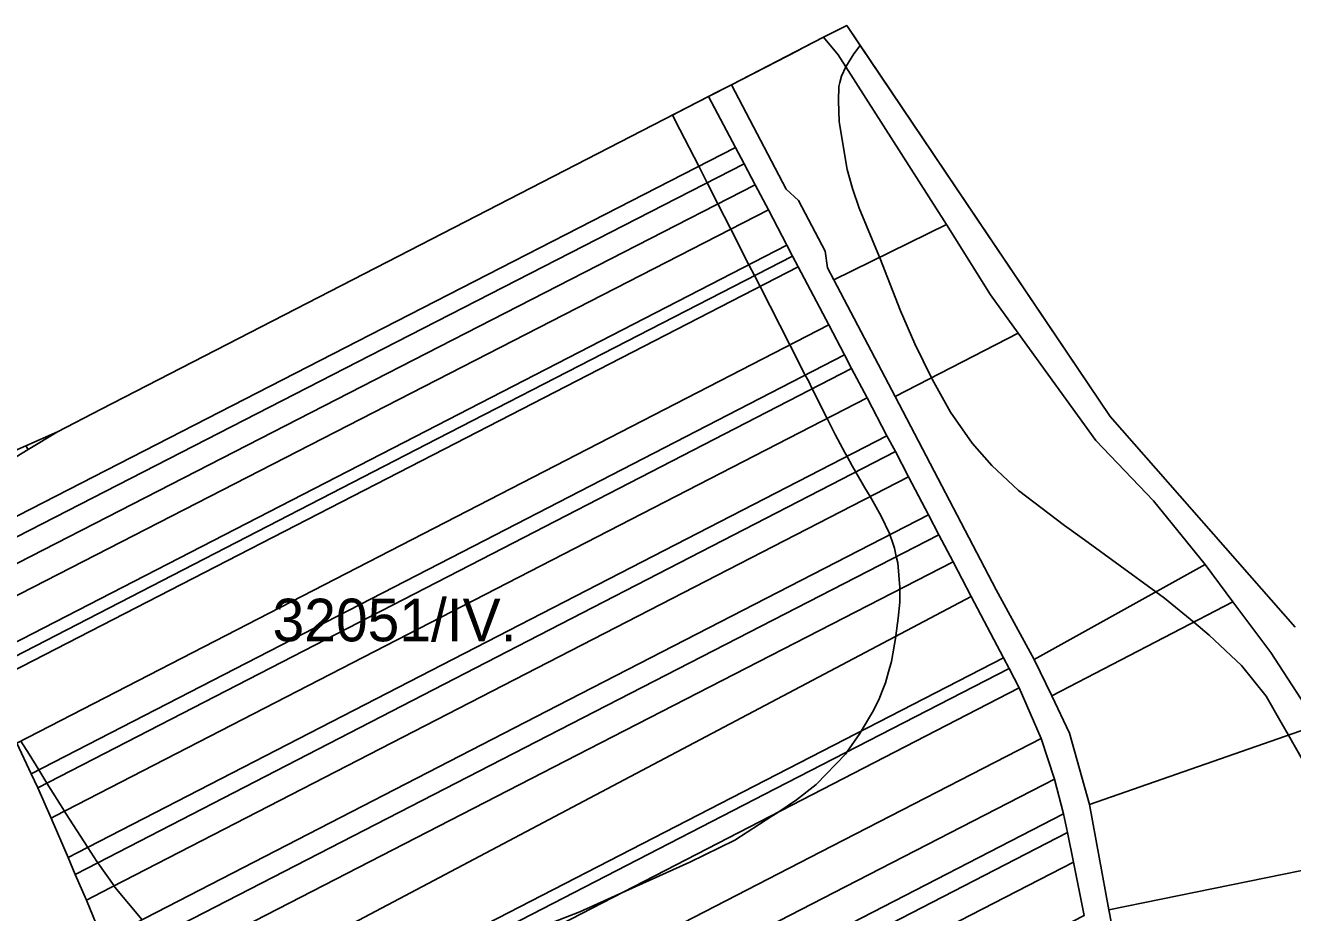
# Model space of a CAD drawing. Extents: x -521939 to -516426, y -1197857 to -1189551.
# Drawn here: x -520824.9 to -520378.7, y -1189863.1 to -1189550.7 of the extents above; entities that cross this region are included whole.
import ezdxf

# ---------------------------------------------------------------- set-up
doc = ezdxf.new("R2010")
doc.units = 0
for name, color, linetype in [('95560013', 7, 'Continuous'), ('95640013', 7, 'Continuous'), ('95660013', 7, 'Continuous')]:
    doc.layers.add(name, color=color, linetype=linetype)

msp = doc.modelspace()

# ---------------------------------------------------------------- linework, layer by layer
at = {"layer": '95560013'}
for points in [[(-520552.66, -1189612.4), (-520557.02, -1189608.4), (-520576.33, -1189571.62), (-520543.9, -1189554.92), (-520538.7, -1189561.06), (-520500.57, -1189620.82), (-520540.29, -1189640.25), (-520542.46, -1189636.12), (-520543.28, -1189630.26)], [(-520871.46, -1189729.85), (-520861.25, -1189722.78), (-520845.5, -1189713.21), (-520835.28, -1189707), (-520830.24, -1189703.94), (-520823.89, -1189700.08), (-520813.62, -1189693.84), (-520798.15, -1189685.87), (-520693.52, -1189631.98), (-520584.33, -1189575.74), (-520574.91, -1189593.69), (-520698.86, -1189657.27), (-520862.97, -1189741.45)], [(-520574.91, -1189593.69), (-520571.87, -1189599.49), (-520698.91, -1189664.62), (-520859.09, -1189746.74), (-520862.97, -1189741.45), (-520698.86, -1189657.27)], [(-520571.87, -1189599.49), (-520567.98, -1189606.88), (-520692.96, -1189670.96), (-520854.49, -1189753.78), (-520859.09, -1189746.74), (-520698.91, -1189664.62)], [(-520567.98, -1189606.88), (-520563.29, -1189615.69), (-520689.07, -1189680.22), (-520848.98, -1189762.26), (-520854.49, -1189753.78), (-520692.96, -1189670.96)], [(-520563.29, -1189615.69), (-520556.78, -1189628.12), (-520695.46, -1189699.52), (-520842.22, -1189775.08), (-520848.98, -1189762.26), (-520689.07, -1189680.22)], [(-520475.34, -1189659.1), (-520518.67, -1189681.41), (-520540.29, -1189640.25), (-520500.57, -1189620.82), (-520485.08, -1189645.55)], [(-520556.78, -1189628.12), (-520554.77, -1189631.94), (-520679.88, -1189696.34), (-520840.25, -1189778.89), (-520842.22, -1189775.08), (-520695.46, -1189699.52)], [(-520554.77, -1189631.94), (-520552.78, -1189635.77), (-520677.43, -1189699.92), (-520838.28, -1189782.7), (-520840.25, -1189778.89), (-520679.88, -1189696.34)], [(-520552.78, -1189635.77), (-520542.06, -1189656.2), (-520665.51, -1189719.78), (-520827.89, -1189803.41), (-520838.28, -1189782.7), (-520677.43, -1189699.92)], [(-520542.06, -1189656.2), (-520536.5, -1189666.75), (-520663.27, -1189732.03), (-520822.82, -1189814.19), (-520827.89, -1189803.41), (-520665.51, -1189719.78)], [(-520483.13, -1189749.49), (-520518.67, -1189681.41), (-520475.34, -1189659.1), (-520448.02, -1189696.82), (-520427.67, -1189718.16), (-520409.45, -1189740.47), (-520469.68, -1189773.95)], [(-520536.5, -1189666.75), (-520533.97, -1189671.56), (-520660.56, -1189736.75), (-520820.55, -1189819.14), (-520822.82, -1189814.19), (-520663.27, -1189732.03)], [(-520533.97, -1189671.56), (-520528.55, -1189681.89), (-520655.3, -1189747.14), (-520814.5, -1189829.1), (-520815.85, -1189829.79), (-520820.55, -1189819.14), (-520660.56, -1189736.75)], [(-520528.55, -1189681.89), (-520521.58, -1189695.28), (-520650.79, -1189761.81), (-520806.61, -1189842.04), (-520809.87, -1189843.72), (-520815.85, -1189829.79), (-520814.5, -1189829.1), (-520655.3, -1189747.14)], [(-520824.7, -1189698.73), (-520813.62, -1189693.84), (-520823.89, -1189700.08)], [(-520830.24, -1189703.94), (-520831.59, -1189701.76), (-520824.7, -1189698.73), (-520823.89, -1189700.08)], [(-520521.58, -1189695.28), (-520518.55, -1189700.78), (-520647.83, -1189767.41), (-520803.28, -1189847.53), (-520807.32, -1189849.61), (-520809.87, -1189843.72), (-520806.61, -1189842.04), (-520650.79, -1189761.81)], [(-520518.55, -1189700.78), (-520513.98, -1189709.68), (-520644.86, -1189777.06), (-520798.15, -1189855.98), (-520803.4, -1189858.68), (-520807.32, -1189849.61), (-520803.28, -1189847.53), (-520647.83, -1189767.41)], [(-520798.15, -1189855.98), (-520644.86, -1189777.06), (-520513.98, -1189709.68), (-520506.96, -1189723.04), (-520637.42, -1189790.22), (-520790.27, -1189868.93), (-520797.65, -1189872.73), (-520803.4, -1189858.68)], [(-520506.96, -1189723.04), (-520503.29, -1189730.03), (-520636.85, -1189798.78), (-520786.17, -1189875.64), (-520793.8, -1189879.57), (-520797.65, -1189872.73), (-520790.27, -1189868.93), (-520637.42, -1189790.22)], [(-520503.29, -1189730.03), (-520498.25, -1189739.55), (-520626.56, -1189805.56), (-520780.58, -1189884.8), (-520788.07, -1189888.65), (-520793.8, -1189879.57), (-520786.17, -1189875.64), (-520636.85, -1189798.78)], [(-520764.56, -1189895.88), (-520772.63, -1189897.76), (-520781.3, -1189895.57), (-520785.91, -1189890.86), (-520788.07, -1189888.65), (-520780.58, -1189884.8), (-520626.56, -1189805.56), (-520498.25, -1189739.55), (-520491.89, -1189751.79), (-520605.81, -1189811.99)], [(-520463.47, -1189786.79), (-520469.68, -1189773.95), (-520409.45, -1189740.47), (-520399.82, -1189753.72)], [(-520764.56, -1189895.88), (-520605.81, -1189811.99), (-520491.89, -1189751.79), (-520480.47, -1189773.36), (-520568.34, -1189818.61), (-520729.38, -1189901.54), (-520741.72, -1189895.94), (-520753.69, -1189893.86)], [(-520463.47, -1189786.79), (-520399.82, -1189753.72), (-520386.38, -1189771.5), (-520374.37, -1189789.92), (-520371.11, -1189797.47), (-520450.25, -1189825.06), (-520457.28, -1189799.95)], [(-520478.5, -1189777.12), (-520560.86, -1189819.55), (-520724.92, -1189904.07), (-520727.89, -1189902.2), (-520729.38, -1189901.54), (-520568.34, -1189818.61), (-520480.47, -1189773.36)], [(-520717.89, -1189909.3), (-520722.93, -1189905.34), (-520724.92, -1189904.07), (-520560.86, -1189819.55), (-520478.5, -1189777.12), (-520474.96, -1189783.97), (-520558.87, -1189827.26)], [(-520717.89, -1189909.3), (-520558.87, -1189827.26), (-520474.96, -1189783.97), (-520467.22, -1189801.74), (-520544.77, -1189841.69), (-520704.82, -1189924.14), (-520710.73, -1189916.79)], [(-520358.66, -1189826.35), (-520351.31, -1189843.38), (-520443.42, -1189862.15), (-520450.25, -1189825.06), (-520371.11, -1189797.47)], [(-520704.82, -1189924.14), (-520544.77, -1189841.69), (-520467.22, -1189801.74), (-520462.52, -1189816.05), (-520540.17, -1189856.03), (-520699.84, -1189938.24)], [(-520699.84, -1189938.24), (-520540.17, -1189856.03), (-520462.52, -1189816.05), (-520459.4, -1189828.36), (-520537.7, -1189868.68), (-520697.31, -1189950.87)], [(-520697.31, -1189950.87), (-520537.7, -1189868.68), (-520459.4, -1189828.36), (-520457.93, -1189834.89), (-520545.78, -1189880.13), (-520696.76, -1189957.88)], [(-520696.76, -1189957.88), (-520545.78, -1189880.13), (-520457.93, -1189834.89), (-520455.88, -1189845.31), (-520535.92, -1189886.5), (-520696, -1189968.88)], [(-520696, -1189968.88), (-520535.92, -1189886.5), (-520455.88, -1189845.31), (-520452.13, -1189864.14), (-520538.28, -1189908.5), (-520695.16, -1189989.28)], [(-520443.42, -1189862.15), (-520351.31, -1189843.38), (-520346.91, -1189853.63), (-520344.39, -1189866.49), (-520438.94, -1189885.01)]]:
    msp.add_lwpolyline(points, close=True, dxfattribs=at)
at = {"layer": '95640013'}
for points in [[(-520374.37, -1189789.92), (-520386.38, -1189771.5), (-520399.82, -1189753.72), (-520409.45, -1189740.47), (-520427.67, -1189718.16), (-520448.02, -1189696.82), (-520475.34, -1189659.1), (-520485.08, -1189645.55), (-520500.57, -1189620.82), (-520538.7, -1189561.06), (-520543.9, -1189554.92), (-520541.98, -1189553.93), (-520535.72, -1189550.71), (-520442.97, -1189688.4), (-520377.81, -1189762.57)], [(-520452.13, -1189864.14), (-520455.88, -1189845.31), (-520457.93, -1189834.89), (-520459.4, -1189828.36), (-520462.52, -1189816.05), (-520467.22, -1189801.74), (-520474.96, -1189783.97), (-520478.5, -1189777.12), (-520480.47, -1189773.36), (-520491.89, -1189751.79), (-520498.25, -1189739.55), (-520503.29, -1189730.03), (-520506.96, -1189723.04), (-520513.98, -1189709.68), (-520518.55, -1189700.78), (-520521.58, -1189695.28), (-520528.55, -1189681.89), (-520533.97, -1189671.56), (-520536.5, -1189666.75), (-520542.06, -1189656.2), (-520552.78, -1189635.77), (-520554.77, -1189631.94), (-520556.78, -1189628.12), (-520563.29, -1189615.69), (-520567.98, -1189606.88), (-520571.87, -1189599.49), (-520574.91, -1189593.69), (-520584.33, -1189575.74), (-520576.33, -1189571.62), (-520557.02, -1189608.4), (-520552.66, -1189612.4), (-520543.28, -1189630.26), (-520542.46, -1189636.12), (-520540.29, -1189640.25), (-520518.67, -1189681.41), (-520483.13, -1189749.49), (-520469.68, -1189773.95), (-520463.47, -1189786.79), (-520457.28, -1189799.95), (-520450.25, -1189825.06), (-520443.42, -1189862.15), (-520438.94, -1189885.01)], [(-520827.89, -1189803.41), (-520822.82, -1189814.19), (-520820.55, -1189819.14), (-520815.85, -1189829.79), (-520809.87, -1189843.72), (-520807.32, -1189849.61), (-520803.4, -1189858.68), (-520797.65, -1189872.73)]]:
    msp.add_lwpolyline(points, dxfattribs=at)
at = {"layer": '95660013'}
for points in [[(-520576.33, -1189571.62), (-520552.83, -1189559.52), (-520551.14, -1189558.65), (-520543.9, -1189554.92), (-520541.98, -1189553.93), (-520535.72, -1189550.71), (-520530.95, -1189557.79), (-520533.24, -1189560.76), (-520536.01, -1189565.26), (-520537.53, -1189568.65), (-520538.09, -1189570.83), (-520538.46, -1189572.24), (-520538.57, -1189577.34), (-520538.34, -1189584.53), (-520538.22, -1189585.25), (-520537.06, -1189592.41), (-520535.56, -1189601.45), (-520533.7, -1189608.17), (-520531.27, -1189615.13), (-520524.15, -1189632.35), (-520524.08, -1189632.51), (-520516.78, -1189651.18), (-520511.68, -1189662.88), (-520505.87, -1189674.82), (-520505.65, -1189675.28), (-520499.16, -1189686.88), (-520491.51, -1189697.77), (-520484.67, -1189705.65), (-520475.17, -1189714.46), (-520459.06, -1189726.75), (-520451.98, -1189731.89), (-520426.87, -1189750.15), (-520423.82, -1189752.37), (-520413.53, -1189760.84), (-520408.06, -1189765.35), (-520396.7, -1189776.13), (-520388, -1189786.91), (-520382.72, -1189796.16), (-520380.17, -1189800.63), (-520375.25, -1189809.28)], [(-520375.25, -1189809.28), (-520380.17, -1189800.63), (-520382.72, -1189796.16), (-520388, -1189786.91), (-520396.7, -1189776.13), (-520408.06, -1189765.35), (-520413.53, -1189760.84), (-520423.82, -1189752.37), (-520426.87, -1189750.15), (-520451.98, -1189731.89), (-520459.06, -1189726.75), (-520475.17, -1189714.46), (-520484.67, -1189705.65), (-520491.51, -1189697.77), (-520499.16, -1189686.88), (-520505.65, -1189675.28), (-520505.87, -1189674.82), (-520511.68, -1189662.88), (-520516.78, -1189651.18), (-520524.08, -1189632.51), (-520524.15, -1189632.35), (-520531.27, -1189615.13), (-520533.7, -1189608.17), (-520535.56, -1189601.45), (-520537.06, -1189592.41), (-520538.22, -1189585.25), (-520538.34, -1189584.53), (-520538.57, -1189577.34), (-520538.46, -1189572.24), (-520538.09, -1189570.83), (-520537.53, -1189568.65), (-520536.01, -1189565.26), (-520533.24, -1189560.76), (-520530.95, -1189557.79), (-520442.97, -1189688.4), (-520377.81, -1189762.57)], [(-520650.58, -1189870.93), (-520629.7, -1189862.77), (-520613.56, -1189855.48), (-520590.98, -1189845.27), (-520575.12, -1189837.57), (-520562.05, -1189829.17), (-520560.36, -1189828.03), (-520553.42, -1189823.34), (-520546.42, -1189817.98), (-520536.04, -1189807.13), (-520535.65, -1189806.56), (-520531.14, -1189800.01), (-520530.66, -1189799.2), (-520526.62, -1189792.49), (-520524.38, -1189788.17), (-520523.18, -1189785.12), (-520522.04, -1189782.23), (-520520.95, -1189778.28), (-520519.95, -1189774.64), (-520518.46, -1189765.83), (-520518.43, -1189765.66), (-520517.61, -1189759.42), (-520517.03, -1189753.82), (-520517.03, -1189749.21), (-520517.03, -1189748.58), (-520517.73, -1189739.94), (-520518.24, -1189737.72), (-520518.9, -1189734.81), (-520519.5, -1189733), (-520520.49, -1189730.01), (-520520.64, -1189729.56), (-520523.56, -1189723.5), (-520525.89, -1189719.3), (-520527.46, -1189716.62), (-520529.28, -1189713.53), (-520532.53, -1189707.99), (-520533.83, -1189705.77), (-520535.6, -1189702.5), (-520536.23, -1189701.34), (-520539.77, -1189694.8), (-520542.61, -1189689.13), (-520547.83, -1189678.7), (-520549.22, -1189675.91), (-520550.28, -1189673.84), (-520555.7, -1189663.22), (-520566.2, -1189642.67), (-520568.16, -1189638.83), (-520570.12, -1189634.99), (-520576.51, -1189622.47), (-520581.05, -1189613.58), (-520584.85, -1189606.15), (-520587.83, -1189600.32), (-520594.43, -1189587.39), (-520597.03, -1189582.29), (-520595.05, -1189581.27), (-520587.82, -1189577.54), (-520584.33, -1189575.74), (-520581.39, -1189574.23), (-520576.33, -1189571.62)], [(-520831.59, -1189701.76), (-520824.7, -1189698.73), (-520813.62, -1189693.84), (-520798.15, -1189685.87), (-520693.52, -1189631.98), (-520584.33, -1189575.74), (-520587.82, -1189577.54), (-520595.05, -1189581.27), (-520597.03, -1189582.29), (-520594.43, -1189587.39), (-520587.83, -1189600.32), (-520584.85, -1189606.15), (-520581.05, -1189613.58), (-520576.51, -1189622.47), (-520570.12, -1189634.99), (-520568.16, -1189638.83), (-520566.2, -1189642.67), (-520555.7, -1189663.22), (-520550.28, -1189673.84), (-520549.22, -1189675.91), (-520547.83, -1189678.7), (-520542.61, -1189689.13), (-520539.77, -1189694.8), (-520536.23, -1189701.34), (-520535.6, -1189702.5), (-520533.83, -1189705.77), (-520532.53, -1189707.99), (-520529.28, -1189713.53), (-520527.46, -1189716.62), (-520525.89, -1189719.3), (-520523.56, -1189723.5), (-520520.64, -1189729.56), (-520520.49, -1189730.01), (-520519.5, -1189733), (-520518.9, -1189734.81), (-520518.24, -1189737.72), (-520517.73, -1189739.94), (-520517.03, -1189748.58), (-520517.03, -1189749.21), (-520517.03, -1189753.82), (-520517.61, -1189759.42), (-520518.43, -1189765.66), (-520518.46, -1189765.83), (-520519.95, -1189774.64), (-520520.95, -1189778.28), (-520522.04, -1189782.23), (-520523.18, -1189785.12), (-520524.38, -1189788.17), (-520526.62, -1189792.49), (-520530.66, -1189799.2), (-520531.14, -1189800.01), (-520535.65, -1189806.56), (-520536.04, -1189807.13), (-520546.42, -1189817.98), (-520553.42, -1189823.34), (-520560.36, -1189828.03), (-520562.05, -1189829.17), (-520575.12, -1189837.57), (-520590.98, -1189845.27), (-520613.56, -1189855.48), (-520629.7, -1189862.77), (-520650.58, -1189870.93)], [(-520783.81, -1189865.6), (-520793.35, -1189854.13), (-520793.67, -1189853.67), (-520799.41, -1189845.54), (-520799.76, -1189845.04), (-520802.92, -1189840.14), (-520810.61, -1189828.24), (-520811.15, -1189827.37), (-520817.29, -1189817.46), (-520820.17, -1189812.82), (-520823.56, -1189807.36), (-520826.49, -1189802.69)], [(-520826.49, -1189802.69), (-520823.56, -1189807.36), (-520820.17, -1189812.82), (-520817.29, -1189817.46), (-520811.15, -1189827.37), (-520810.61, -1189828.24), (-520802.92, -1189840.14), (-520799.76, -1189845.04), (-520799.41, -1189845.54), (-520793.67, -1189853.67), (-520793.35, -1189854.13), (-520783.81, -1189865.6)]]:
    msp.add_lwpolyline(points, dxfattribs=at)

# ---------------------------------------------------------------- texts
msp.add_text('32051/IV.', height=15, rotation=0, dxfattribs=at).set_placement((-520737.85, -1189767.57))

doc.saveas('drawing.dxf')
